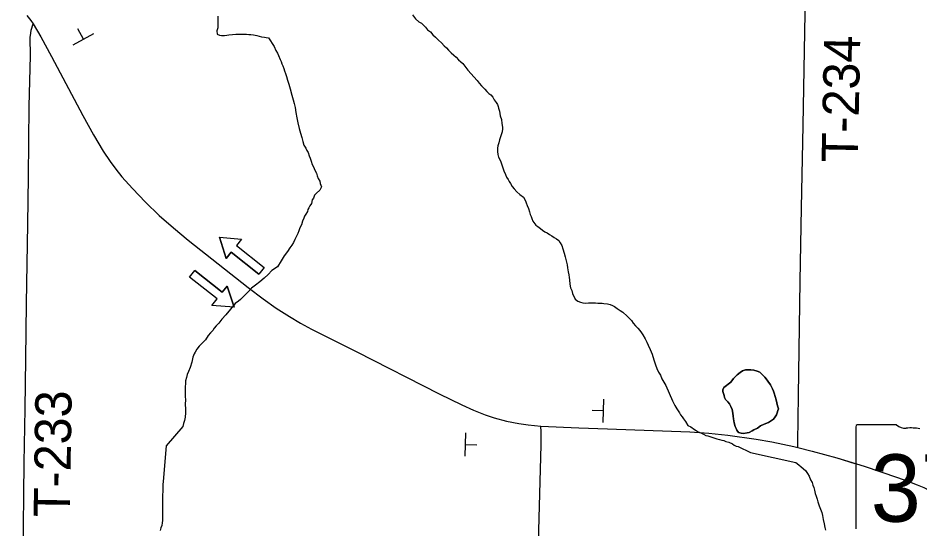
# Model space of a CAD drawing. Extents: x 1 to 1675, y -2 to 1113.
# Drawn here: x 1660.49 to 1666.71, y 1095.04 to 1098.56 of the extents above; entities that cross this region are included whole.
import ezdxf

# ---------------------------------------------------------------- set-up
doc = ezdxf.new("R2010")
doc.units = 0
for name, color, linetype in [('GM_X_State_Route', 7, 'Continuous'), ('GM_X_State_Shield', 7, 'Continuous'), ('GM_X_Township_Road_Text', 7, 'Continuous'), ('SC_Scratch1', 7, 'Continuous'), ('SH_Text', 7, 'Continuous'), ('SN_P_Signs', 7, 'Continuous'), ('SN_P_Text', 7, 'Continuous')]:
    doc.layers.add(name, color=color, linetype=linetype)

msp = doc.modelspace()

# ---------------------------------------------------------------- linework, layer by layer
at = {"layer": 'GM_X_State_Route'}
for points in [[(1660.552, 1098.5772), (1660.5797, 1098.5427), (1660.5954, 1098.5194), (1660.6489, 1098.43), (1660.7226, 1098.2955), (1660.9376, 1097.8891), (1661.0117, 1097.7552), (1661.0794, 1097.643), (1661.1276, 1097.5702), (1661.1659, 1097.5174), (1661.2071, 1097.4667), (1661.2796, 1097.3852), (1661.3708, 1097.2909), (1661.4653, 1097.2001), (1661.5635, 1097.1133), (1661.6646, 1097.0297), (1662.0769, 1096.7044), (1662.1816, 1096.6253), (1662.2705, 1096.5618), (1662.3621, 1096.5026), (1662.4371, 1096.4581), (1662.5141, 1096.417), (1662.8274, 1096.2607), (1663.3928, 1095.972), (1663.5499, 1095.8949), (1663.6295, 1095.859), (1663.7106, 1095.8271), (1663.7726, 1095.8067), (1663.8567, 1095.7839), (1663.9422, 1095.767), (1664.0068, 1095.7573), (1664.0954, 1095.7491), (1664.3558, 1095.737), (1664.5527, 1095.7309), (1665.1216, 1095.7091), (1665.2528, 1095.6999), (1665.3836, 1095.6854), (1665.5789, 1095.6584), (1665.6871, 1095.6403), (1665.8373, 1095.6085), (1665.8647, 1095.6018)], [(1665.8647, 1095.6018), (1665.965, 1095.5772), (1666.134, 1095.5304), (1666.3224, 1095.4721), (1666.5511, 1095.3957), (1666.6338, 1095.3657), (1666.6887, 1095.3448), (1666.7333, 1095.3248), (1666.7723, 1095.3047), (1666.8024, 1095.2846), (1666.8281, 1095.2635), (1666.8616, 1095.2312), (1666.8894, 1095.1977), (1666.9173, 1095.1598), (1666.966, 1095.0892), (1667.036, 1094.9775), (1667.3422, 1094.472), (1667.5124, 1094.191), (1667.5577, 1094.1145), (1667.6338, 1093.9829), (1667.8558, 1093.5802), (1667.8763, 1093.5432)]]:
    msp.add_lwpolyline(points, dxfattribs=at)
at = {"layer": 'GM_X_State_Shield'}
for p, q in [((1666.5457, 1095.7569), (1666.2739, 1095.7569)), ((1666.2648, 1095.7448), (1666.2648, 1095.0404))]:
    msp.add_line(p, q, dxfattribs=at)
for centre, radius, start, end in [((1666.2754, 1095.7463), 0.0108, 98.1301, 188.1301), ((1666.6104, 1095.8387), 0.1043, 231.61951, 271.11188), ((1666.645, 1095.3615), 0.3744, 80.48669, 94.98827)]:
    msp.add_arc(centre, radius, start, end, dxfattribs=at)
at = {"layer": 'SC_Scratch1'}
for points in [[(1661.8687, 1098.5713), (1661.8683, 1098.5418), (1661.8677, 1098.4909), (1661.8621, 1098.4723), (1661.8645, 1098.4481), (1661.8805, 1098.4426), (1661.8939, 1098.4397), (1661.9154, 1098.4394), (1661.9315, 1098.4419), (1661.945, 1098.4444), (1661.9692, 1098.4467), (1661.9934, 1098.4491), (1662.0095, 1098.4489), (1662.0256, 1098.4487), (1662.039, 1098.4485), (1662.0659, 1098.4482), (1662.0819, 1098.4453), (1662.0954, 1098.4451), (1662.1142, 1098.4449), (1662.1383, 1098.4392), (1662.1543, 1098.4336), (1662.1704, 1098.4307), (1662.1891, 1098.4278), (1662.2025, 1098.4249), (1662.2186, 1098.4221), (1662.2555, 1098.3626), (1662.2685, 1098.3357), (1662.2791, 1098.3168), (1662.2869, 1098.3006), (1662.2973, 1098.2737), (1662.3052, 1098.2602), (1662.3104, 1098.2441), (1662.3156, 1098.2306), (1662.3234, 1098.2117), (1662.3286, 1098.1956), (1662.3337, 1098.1768), (1662.3415, 1098.1579), (1662.3492, 1098.1311), (1662.3569, 1098.1042), (1662.3673, 1098.0719), (1662.3775, 1098.0289), (1662.3878, 1097.9966), (1662.3955, 1097.9697), (1662.4006, 1097.9429), (1662.4055, 1097.908), (1662.4131, 1097.8731), (1662.4207, 1097.8381), (1662.4283, 1097.7979), (1662.4386, 1097.7656), (1662.4463, 1097.736), (1662.454, 1097.7091), (1662.4618, 1097.6849), (1662.4749, 1097.6633), (1662.4828, 1097.6471), (1662.4907, 1097.6336)], [(1663.2089, 1098.5805), (1663.23, 1098.5535), (1663.254, 1098.5344), (1663.2726, 1098.5234), (1663.2859, 1098.5099), (1663.2991, 1098.4963), (1663.3123, 1098.4774), (1663.3336, 1098.4637), (1663.3495, 1098.4447), (1663.3681, 1098.4284), (1663.3893, 1098.4067), (1663.4106, 1098.3877), (1663.4291, 1098.3687), (1663.4451, 1098.3551), (1663.4583, 1098.3388), (1663.4769, 1098.3198), (1663.4954, 1098.3035), (1663.5114, 1098.2899), (1663.5273, 1098.271), (1663.5432, 1098.2574), (1663.5565, 1098.2465), (1663.5697, 1098.2275), (1663.5908, 1098.2005), (1663.6544, 1098.13), (1663.6703, 1098.1111), (1663.6861, 1098.0921), (1663.7073, 1098.0704), (1663.7233, 1098.0541), (1663.7365, 1098.0405), (1663.7498, 1098.0297), (1663.763, 1098.0134), (1663.7736, 1097.9972), (1663.7868, 1097.9783), (1663.7947, 1097.9648), (1663.7998, 1097.9513), (1663.8024, 1097.9379), (1663.8102, 1097.919), (1663.8151, 1097.8868), (1663.8229, 1097.8599), (1663.8252, 1097.8331), (1663.8303, 1097.8089), (1663.8301, 1097.7956), (1663.8272, 1097.7768), (1663.8243, 1097.7608), (1663.8188, 1097.7475), (1663.8132, 1097.7342), (1663.8104, 1097.7208), (1663.8047, 1097.6994), (1663.7991, 1097.6781), (1663.7962, 1097.6621), (1663.7959, 1097.6406), (1663.7983, 1097.6192), (1663.8035, 1097.6004), (1663.8113, 1097.5842), (1663.8192, 1097.568), (1663.8269, 1097.5411), (1663.8399, 1097.5061), (1663.8503, 1097.4819), (1663.8582, 1097.463), (1663.8687, 1097.4468), (1663.8766, 1097.4333), (1663.8845, 1097.4198), (1663.8976, 1097.3982), (1663.9108, 1097.382), (1663.9294, 1097.363), (1663.9506, 1097.344), (1663.9746, 1097.3249), (1663.9877, 1097.3006), (1663.9929, 1097.2871), (1664.0007, 1097.2683), (1664.0085, 1097.2468), (1664.0163, 1097.2252), (1664.0214, 1097.2064), (1664.0266, 1097.1929), (1664.0318, 1097.1795), (1664.0396, 1097.1606), (1664.0608, 1097.1336), (1664.0741, 1097.1227), (1664.0927, 1097.1091), (1664.106, 1097.0982), (1664.122, 1097.0872), (1664.138, 1097.079), (1664.154, 1097.0681), (1664.17, 1097.0598), (1664.1859, 1097.0489), (1664.2019, 1097.038), (1664.2179, 1097.027), (1664.2284, 1097.0108), (1664.2389, 1096.9919), (1664.2467, 1096.9704), (1664.2544, 1096.9408), (1664.2621, 1096.914), (1664.2698, 1096.8871), (1664.2749, 1096.8602), (1664.2773, 1096.8388), (1664.2823, 1096.8119), (1664.2874, 1096.7904), (1664.2899, 1096.7716), (1664.2923, 1096.7555), (1664.2947, 1096.726)], [(1662.4907, 1097.6336), (1662.4984, 1097.6094), (1662.5036, 1097.5933), (1662.5114, 1097.5744), (1662.5192, 1097.5502), (1662.527, 1097.5341), (1662.5375, 1097.5125), (1662.548, 1097.4909), (1662.5531, 1097.4721), (1662.5609, 1097.4532), (1662.5714, 1097.437), (1662.5739, 1097.4209), (1662.5817, 1097.3967), (1662.5706, 1097.3728), (1662.5489, 1097.3543), (1662.5353, 1097.3384), (1662.527, 1097.3198), (1662.5188, 1097.3065), (1662.5131, 1097.2824), (1662.5021, 1097.2665), (1662.4966, 1097.2532), (1662.4884, 1097.2399), (1662.4855, 1097.2265), (1662.4746, 1097.2079), (1662.4663, 1097.1947), (1662.4608, 1097.1813), (1662.4525, 1097.16), (1662.4441, 1097.136), (1662.4331, 1097.1147), (1662.4275, 1097.0934), (1662.4192, 1097.0747), (1662.4109, 1097.0561), (1662.3999, 1097.0348), (1662.3889, 1097.0135), (1662.3779, 1096.9949), (1662.3642, 1096.9763), (1662.3478, 1096.9525), (1662.3259, 1096.9206), (1662.304, 1096.8861), (1662.2793, 1096.8462), (1662.2414, 1096.8199), (1662.2142, 1096.7935), (1662.187, 1096.767), (1662.1572, 1096.7433), (1662.1273, 1096.7196), (1662.1002, 1096.6985), (1662.0757, 1096.6721), (1662.0567, 1096.6536), (1662.0404, 1096.6377), (1662.0241, 1096.6219), (1662.0105, 1096.6086), (1661.9888, 1096.5929), (1661.9234, 1096.516), (1661.8961, 1096.4843), (1661.8743, 1096.4577), (1661.8579, 1096.4392), (1661.8443, 1096.4233), (1661.8334, 1096.4074), (1661.8171, 1096.3915), (1661.8007, 1096.373), (1661.7842, 1096.3437), (1661.7598, 1096.3199), (1661.7407, 1096.2988), (1661.7243, 1096.2776), (1661.7133, 1096.259), (1661.7051, 1096.2457), (1661.6968, 1096.2243), (1661.6883, 1096.1896), (1661.6771, 1096.1523), (1661.666, 1096.1256), (1661.6577, 1096.1043), (1661.652, 1096.083), (1661.6464, 1096.0616), (1661.6461, 1096.0402), (1661.6432, 1096.0215), (1661.6429, 1096.0001), (1661.6426, 1095.9759), (1661.6423, 1095.9518), (1661.6448, 1095.9304), (1661.6444, 1095.9009), (1661.6466, 1095.8661), (1661.6463, 1095.8393), (1661.6432, 1095.8099), (1661.6376, 1095.7885), (1661.6319, 1095.7671), (1661.6263, 1095.7458), (1661.5131, 1095.613)], [(1664.2947, 1096.726), (1664.2997, 1096.7019), (1664.3075, 1096.683), (1664.3127, 1096.6615), (1664.331, 1096.6238), (1664.3496, 1096.6101), (1664.3683, 1096.6018), (1664.3844, 1096.5989), (1664.4005, 1096.5961), (1664.422, 1096.5985), (1664.4381, 1096.5982), (1664.4542, 1096.598), (1664.4703, 1096.5978), (1664.4864, 1096.5949), (1664.4998, 1096.5948), (1664.5159, 1096.5945), (1664.5293, 1096.5944), (1664.5535, 1096.5914), (1664.5722, 1096.5858), (1664.5882, 1096.5802), (1664.6016, 1096.572), (1664.6202, 1096.5584), (1664.6415, 1096.5447), (1664.6602, 1096.5337), (1664.6894, 1096.5066), (1664.7026, 1096.493), (1664.7185, 1096.4767), (1664.7317, 1096.4578), (1664.7476, 1096.4388), (1664.7635, 1096.4225), (1664.7767, 1096.4063), (1664.7873, 1096.3901), (1664.7978, 1096.3766), (1664.8136, 1096.3496), (1664.8241, 1096.328), (1664.8345, 1096.3064), (1664.8476, 1096.2768), (1664.8606, 1096.2445), (1664.8735, 1096.2041), (1664.8839, 1096.1719), (1664.8943, 1096.1449), (1664.9047, 1096.1207), (1664.9179, 1096.0991), (1664.9283, 1096.0748), (1664.9414, 1096.0506), (1664.9546, 1096.029), (1665.0016, 1095.9239), (1665.0173, 1095.8915), (1665.0304, 1095.8672), (1665.041, 1095.8537), (1665.0489, 1095.8402), (1665.0568, 1095.8267), (1665.0674, 1095.8132), (1665.0779, 1095.7997), (1665.0911, 1095.7807), (1665.1069, 1095.7537), (1665.1282, 1095.7427), (1665.1522, 1095.7263), (1665.1655, 1095.7181), (1665.1788, 1095.7099), (1665.1975, 1095.7017), (1665.2162, 1095.6934), (1665.2322, 1095.6851), (1665.2456, 1095.6823), (1665.259, 1095.6767), (1665.2804, 1095.6711), (1665.3071, 1095.66), (1665.3259, 1095.6571), (1665.3419, 1095.6515), (1665.3553, 1095.6487), (1665.3687, 1095.6432), (1665.3901, 1095.6375), (1665.4141, 1095.6265), (1665.4275, 1095.6183), (1665.4408, 1095.6101), (1665.4542, 1095.6072), (1665.5385, 1095.568)], [(1661.5131, 1095.613), (1661.4928, 1095.3669), (1661.4901, 1095.3455), (1661.49, 1095.3241), (1661.49, 1095.3027), (1661.4872, 1095.2706), (1661.4872, 1095.2465), (1661.4871, 1095.2144), (1661.487, 1095.1876), (1661.487, 1095.1635), (1661.4869, 1095.1421), (1661.4869, 1095.1207), (1661.4869, 1095.0993), (1661.4841, 1095.0833), (1661.4814, 1095.0646), (1661.476, 1095.0485), (1661.4706, 1095.0298)], [(1665.5385, 1095.568), (1665.852, 1095.4974), (1665.8733, 1095.4813), (1665.8894, 1095.4679), (1665.9187, 1095.4437), (1665.9321, 1095.4222), (1665.9427, 1095.4035), (1665.9534, 1095.3794), (1665.964, 1095.3606), (1665.9693, 1095.3419), (1665.9747, 1095.3258), (1665.98, 1095.307), (1665.9853, 1095.2856), (1665.9906, 1095.2669), (1665.9986, 1095.2454), (1666.0039, 1095.2267), (1666.0118, 1095.1999), (1666.0225, 1095.1758), (1666.0305, 1095.1544), (1666.0358, 1095.1329), (1666.041, 1095.1062), (1666.0463, 1095.0767), (1666.0516, 1095.05), (1666.0569, 1095.0312)]]:
    msp.add_lwpolyline(points, dxfattribs=at)
at = {"layer": 'SH_Text'}
for p, q in [((1661.8798, 1097.0493), (1662.0324, 1097.0366)), ((1661.8798, 1097.0493), (1661.927, 1096.9037)), ((1662.0324, 1097.0366), (1661.997, 1096.9919)), ((1661.997, 1096.9919), (1662.1867, 1096.8416)), ((1661.927, 1096.9037), (1661.9609, 1096.9465)), ((1661.9609, 1096.9465), (1662.1507, 1096.7962)), ((1661.6735, 1096.7752), (1661.7095, 1096.8207)), ((1661.8993, 1096.6704), (1661.7095, 1096.8207)), ((1662.1867, 1096.8416), (1662.1507, 1096.7962)), ((1661.8632, 1096.6249), (1661.6735, 1096.7752)), ((1661.9331, 1096.7131), (1661.8993, 1096.6704)), ((1661.9804, 1096.5675), (1661.9331, 1096.7131)), ((1661.8278, 1096.5802), (1661.8632, 1096.6249)), ((1661.9804, 1096.5675), (1661.8278, 1096.5802))]:
    msp.add_line(p, q, dxfattribs=at)
for points in [[(1660.552, 1098.5772), (1660.5797, 1098.5427), (1660.5954, 1098.5194), (1660.6489, 1098.43), (1660.7226, 1098.2955), (1660.9376, 1097.8891), (1661.0117, 1097.7552), (1661.0794, 1097.643), (1661.1276, 1097.5702), (1661.1659, 1097.5174), (1661.2071, 1097.4667), (1661.2796, 1097.3852), (1661.3708, 1097.2909), (1661.4653, 1097.2001), (1661.5635, 1097.1133), (1661.6646, 1097.0297), (1662.0769, 1096.7044), (1662.1816, 1096.6253), (1662.2705, 1096.5618), (1662.3621, 1096.5026), (1662.4371, 1096.4581), (1662.5141, 1096.417), (1662.8274, 1096.2607), (1663.3928, 1095.972), (1663.5499, 1095.8949), (1663.6295, 1095.859), (1663.7106, 1095.8271), (1663.7726, 1095.8067), (1663.8567, 1095.7839), (1663.9422, 1095.767), (1664.0068, 1095.7573), (1664.0954, 1095.7491)], [(1660.552, 1098.5772), (1660.5797, 1098.5427), (1660.5954, 1098.5194), (1660.6489, 1098.43), (1660.7226, 1098.2955), (1660.9376, 1097.8891), (1661.0117, 1097.7552), (1661.0794, 1097.643), (1661.1276, 1097.5702), (1661.1659, 1097.5174), (1661.2071, 1097.4667), (1661.2796, 1097.3852), (1661.3708, 1097.2909), (1661.4653, 1097.2001), (1661.5635, 1097.1133), (1661.6646, 1097.0297), (1662.0769, 1096.7044), (1662.1816, 1096.6253), (1662.2705, 1096.5618), (1662.3621, 1096.5026), (1662.4371, 1096.4581), (1662.5141, 1096.417), (1662.8274, 1096.2607), (1663.3928, 1095.972), (1663.5499, 1095.8949), (1663.6295, 1095.859), (1663.7106, 1095.8271), (1663.7726, 1095.8067), (1663.8567, 1095.7839), (1663.9422, 1095.767), (1664.0068, 1095.7573), (1664.0954, 1095.7491), (1664.3558, 1095.737), (1664.5527, 1095.7309), (1665.1216, 1095.7091), (1665.2528, 1095.6999), (1665.3836, 1095.6854), (1665.5789, 1095.6584), (1665.6871, 1095.6403), (1665.8373, 1095.6085), (1665.8647, 1095.6018)], [(1665.3546, 1096.0157), (1665.4034, 1096.0525), (1665.4225, 1096.0764), (1665.447, 1096.1029), (1665.4687, 1096.1186), (1665.4849, 1096.1291), (1665.5038, 1096.1369), (1665.5226, 1096.1367), (1665.5414, 1096.1364), (1665.5628, 1096.1335), (1665.5843, 1096.1279), (1665.6029, 1096.1196), (1665.6242, 1096.1005), (1665.6374, 1096.087), (1665.648, 1096.0734), (1665.6586, 1096.0572), (1665.677, 1096.0329), (1665.6849, 1096.0194), (1665.6901, 1096.0059), (1665.698, 1095.9897), (1665.7032, 1095.9763), (1665.716, 1095.9306), (1665.7211, 1095.9091), (1665.7263, 1095.8876), (1665.7314, 1095.8688), (1665.7285, 1095.8554), (1665.723, 1095.8394), (1665.7174, 1095.8261), (1665.7092, 1095.8128), (1665.6983, 1095.7969), (1665.6847, 1095.7863), (1665.663, 1095.7732), (1665.6334, 1095.7629), (1665.609, 1095.7498), (1665.5873, 1095.734), (1665.563, 1095.7236), (1665.5495, 1095.7158), (1665.5306, 1095.7053), (1665.5171, 1095.7028), (1665.4902, 1095.6978), (1665.4741, 1095.7007), (1665.4554, 1095.7036), (1665.4448, 1095.7198), (1665.4396, 1095.7333), (1665.4344, 1095.7468), (1665.4267, 1095.771), (1665.4242, 1095.7844), (1665.4217, 1095.7978), (1665.4192, 1095.8166), (1665.4168, 1095.8381), (1665.4117, 1095.8622), (1665.4039, 1095.8838), (1665.3934, 1095.9027), (1665.3829, 1095.9162), (1665.3669, 1095.9325), (1665.3591, 1095.946), (1665.3565, 1095.9594), (1665.3488, 1095.9863), (1665.349, 1095.9997), (1665.3546, 1096.0157)], [(1665.3546, 1096.0157), (1665.4034, 1096.0525), (1665.4225, 1096.0764), (1665.447, 1096.1029), (1665.4687, 1096.1186), (1665.4849, 1096.1291), (1665.5038, 1096.1369), (1665.5226, 1096.1367), (1665.5414, 1096.1364), (1665.5628, 1096.1335), (1665.5843, 1096.1279), (1665.6029, 1096.1196), (1665.6242, 1096.1005), (1665.6374, 1096.087), (1665.648, 1096.0734), (1665.6586, 1096.0572), (1665.677, 1096.0329), (1665.6849, 1096.0194), (1665.6901, 1096.0059), (1665.698, 1095.9897), (1665.7032, 1095.9763), (1665.716, 1095.9306), (1665.7211, 1095.9091), (1665.7263, 1095.8876), (1665.7314, 1095.8688), (1665.7285, 1095.8554), (1665.723, 1095.8394), (1665.7174, 1095.8261), (1665.7092, 1095.8128), (1665.6983, 1095.7969), (1665.6847, 1095.7863), (1665.663, 1095.7732), (1665.6334, 1095.7629), (1665.609, 1095.7498), (1665.5873, 1095.734), (1665.563, 1095.7236), (1665.5495, 1095.7158), (1665.5306, 1095.7053), (1665.5171, 1095.7028), (1665.4902, 1095.6978), (1665.4741, 1095.7007), (1665.4554, 1095.7036), (1665.4448, 1095.7198), (1665.4396, 1095.7333), (1665.4344, 1095.7468), (1665.4267, 1095.771), (1665.4242, 1095.7844), (1665.4217, 1095.7978), (1665.4192, 1095.8166), (1665.4168, 1095.8381), (1665.4117, 1095.8622), (1665.4039, 1095.8838), (1665.3934, 1095.9027), (1665.3829, 1095.9162), (1665.3669, 1095.9325), (1665.3591, 1095.946), (1665.3565, 1095.9594), (1665.3488, 1095.9863), (1665.349, 1095.9997), (1665.3546, 1096.0157)], [(1665.6983, 1095.7969), (1665.7092, 1095.8128), (1665.7174, 1095.8261), (1665.723, 1095.8394), (1665.7285, 1095.8554), (1665.7314, 1095.8688), (1665.7263, 1095.8876), (1665.7211, 1095.9091), (1665.716, 1095.9306), (1665.7032, 1095.9763), (1665.698, 1095.9897), (1665.6901, 1096.0059), (1665.6849, 1096.0194), (1665.677, 1096.0329), (1665.6586, 1096.0572), (1665.648, 1096.0734), (1665.6374, 1096.087), (1665.6242, 1096.1005), (1665.6029, 1096.1196), (1665.5843, 1096.1279), (1665.5628, 1096.1335), (1665.5414, 1096.1364), (1665.5226, 1096.1367), (1665.5038, 1096.1369), (1665.4849, 1096.1291), (1665.4687, 1096.1186), (1665.447, 1096.1029), (1665.4225, 1096.0764), (1665.4034, 1096.0525), (1665.3546, 1096.0157)], [(1665.6983, 1095.7969), (1665.7092, 1095.8128), (1665.7174, 1095.8261), (1665.723, 1095.8394), (1665.7285, 1095.8554), (1665.7314, 1095.8688), (1665.7263, 1095.8876), (1665.7211, 1095.9091), (1665.716, 1095.9306), (1665.7032, 1095.9763), (1665.698, 1095.9897), (1665.6901, 1096.0059), (1665.6849, 1096.0194), (1665.677, 1096.0329), (1665.6586, 1096.0572), (1665.648, 1096.0734), (1665.6374, 1096.087), (1665.6242, 1096.1005), (1665.6029, 1096.1196), (1665.5843, 1096.1279), (1665.5628, 1096.1335), (1665.5414, 1096.1364), (1665.5226, 1096.1367), (1665.5038, 1096.1369), (1665.4849, 1096.1291), (1665.4687, 1096.1186), (1665.447, 1096.1029), (1665.4225, 1096.0764), (1665.4034, 1096.0525), (1665.3546, 1096.0157)], [(1665.3546, 1096.0157), (1665.349, 1095.9997), (1665.3488, 1095.9863), (1665.3565, 1095.9594), (1665.3591, 1095.946), (1665.3669, 1095.9325), (1665.3829, 1095.9162), (1665.3934, 1095.9027), (1665.4039, 1095.8838), (1665.4117, 1095.8622), (1665.4168, 1095.8381), (1665.4192, 1095.8166), (1665.4217, 1095.7978), (1665.4242, 1095.7844), (1665.4267, 1095.771), (1665.4344, 1095.7468), (1665.4396, 1095.7333), (1665.4448, 1095.7198), (1665.4554, 1095.7036), (1665.4741, 1095.7007), (1665.4902, 1095.6978), (1665.5171, 1095.7028), (1665.5306, 1095.7053), (1665.5495, 1095.7158), (1665.563, 1095.7236), (1665.5873, 1095.734), (1665.609, 1095.7498), (1665.6334, 1095.7629), (1665.663, 1095.7732), (1665.6847, 1095.7863), (1665.6983, 1095.7969)], [(1665.3546, 1096.0157), (1665.349, 1095.9997), (1665.3488, 1095.9863), (1665.3565, 1095.9594), (1665.3591, 1095.946), (1665.3669, 1095.9325), (1665.3829, 1095.9162), (1665.3934, 1095.9027), (1665.4039, 1095.8838), (1665.4117, 1095.8622), (1665.4168, 1095.8381), (1665.4192, 1095.8166), (1665.4217, 1095.7978), (1665.4242, 1095.7844), (1665.4267, 1095.771), (1665.4344, 1095.7468), (1665.4396, 1095.7333), (1665.4448, 1095.7198), (1665.4554, 1095.7036), (1665.4741, 1095.7007), (1665.4902, 1095.6978), (1665.5171, 1095.7028), (1665.5306, 1095.7053), (1665.5495, 1095.7158), (1665.563, 1095.7236), (1665.5873, 1095.734), (1665.609, 1095.7498), (1665.6334, 1095.7629), (1665.663, 1095.7732), (1665.6847, 1095.7863), (1665.6983, 1095.7969)], [(1665.8647, 1095.6018), (1665.965, 1095.5772), (1666.134, 1095.5304), (1666.2582, 1095.492)]]:
    msp.add_lwpolyline(points, dxfattribs=at)
for points in [[(1662.1506, 1096.7962), (1661.9609, 1096.9465), (1661.927, 1096.9037), (1661.8798, 1097.0493), (1662.0324, 1097.0366), (1661.997, 1096.9919), (1662.1867, 1096.8416)], [(1661.7095, 1096.8207), (1661.8993, 1096.6704), (1661.9332, 1096.7131), (1661.9804, 1096.5675), (1661.8278, 1096.5802), (1661.8632, 1096.6249), (1661.6735, 1096.7752)]]:
    msp.add_lwpolyline(points, close=True, dxfattribs=at)
at = {"layer": 'SN_P_Signs'}
for p, q in [((1660.9427, 1098.414), (1660.9043, 1098.4841)), ((1660.8725, 1098.3756), (1661.0129, 1098.4524)), ((1664.5247, 1095.7747), (1664.5295, 1095.9347)), ((1664.5271, 1095.8547), (1664.4471, 1095.8571)), ((1663.5752, 1095.7014), (1663.5705, 1095.5415)), ((1663.5729, 1095.6214), (1663.6528, 1095.619))]:
    msp.add_line(p, q, dxfattribs=at)
msp.add_lwpolyline([(1663.9663, 1092.2384), (1663.9964, 1092.279), (1664.0163, 1092.3184), (1664.0244, 1092.3391), (1664.0345, 1092.3822), (1664.037, 1092.4043), (1664.0399, 1092.4484), (1664.0401, 1092.7334), (1664.0507, 1093.2364), (1664.0534, 1093.499), (1664.0583, 1093.8051), (1664.0729, 1094.5707), (1664.0814, 1095.0301), (1664.0961, 1095.6206), (1664.0956, 1095.7086), (1664.0954, 1095.7491)], dxfattribs=at)
msp.add_lwpolyline([(1663.9663, 1092.2384), (1663.9964, 1092.279), (1664.0163, 1092.3184), (1664.0244, 1092.3391), (1664.0345, 1092.3822), (1664.037, 1092.4043), (1664.0399, 1092.4484), (1664.0401, 1092.7334), (1664.0507, 1093.2364), (1664.0534, 1093.499), (1664.0583, 1093.8051), (1664.0729, 1094.5707), (1664.0814, 1095.0301), (1664.0961, 1095.6206), (1664.0956, 1095.7086), (1664.0954, 1095.7491)], dxfattribs=at)
at = {"layer": 'SN_P_Text'}
for points in [[(1665.8647, 1095.6018), (1665.8652, 1095.6384), (1665.8691, 1095.9598), (1665.8824, 1096.7478), (1665.891, 1097.2512), (1665.9023, 1097.8203), (1665.9237, 1098.9803), (1665.9265, 1099.243), (1665.9316, 1099.5056), (1665.9414, 1100.206), (1665.9454, 1100.3592), (1665.9448, 1100.4293)], [(1665.8647, 1095.6018), (1665.8652, 1095.6384), (1665.8691, 1095.9598), (1665.8824, 1096.7478), (1665.891, 1097.2512), (1665.9023, 1097.8203), (1665.9237, 1098.9803), (1665.9265, 1099.243), (1665.9316, 1099.5056), (1665.9414, 1100.206), (1665.9454, 1100.3592), (1665.9448, 1100.4293)], [(1660.4916, 1092.3184), (1660.5024, 1093.5021), (1660.5078, 1093.787), (1660.5129, 1094.0937), (1660.5178, 1094.3786), (1660.5219, 1094.6414), (1660.5262, 1094.8383), (1660.5346, 1095.4947), (1660.5405, 1095.8685), (1660.5465, 1096.2115), (1660.5501, 1096.5938), (1660.5584, 1097.1408), (1660.5632, 1097.4654), (1660.5692, 1097.9522), (1660.5764, 1098.3001), (1660.5763, 1098.4243), (1660.58, 1098.4562), (1660.5825, 1098.4759), (1660.5954, 1098.5194)], [(1660.4916, 1092.3184), (1660.5024, 1093.5021), (1660.5078, 1093.787), (1660.5129, 1094.0937), (1660.5178, 1094.3786), (1660.5219, 1094.6414), (1660.5262, 1094.8383), (1660.5346, 1095.4947), (1660.5405, 1095.8685), (1660.5465, 1096.2115), (1660.5501, 1096.5938), (1660.5584, 1097.1408), (1660.5632, 1097.4654), (1660.5692, 1097.9522), (1660.5764, 1098.3001), (1660.5763, 1098.4243), (1660.58, 1098.4562), (1660.5825, 1098.4759), (1660.5954, 1098.5194)]]:
    msp.add_lwpolyline(points, dxfattribs=at)

# ---------------------------------------------------------------- texts
at = {"layer": 'GM_X_State_Shield'}
msp.add_text('37', height=0.46406, dxfattribs=at).set_placement((1666.3678, 1095.0901))
at = {"layer": 'GM_X_Township_Road_Text'}
for s, rotation, p in [('T-234', 88.87238, (1666.2787, 1097.5635)), ('T-233', 89.16098, (1660.8488, 1095.1198))]:
    msp.add_text(s, height=0.25, rotation=rotation, dxfattribs=at).set_placement(p)

doc.saveas('drawing.dxf')
